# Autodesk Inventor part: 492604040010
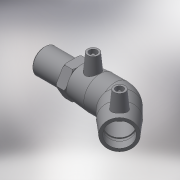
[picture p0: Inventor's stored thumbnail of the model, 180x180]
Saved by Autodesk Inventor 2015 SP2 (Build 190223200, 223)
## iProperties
Created: 2017-06
Part Number: 492604040010
Material: Generic
Description: PLASSON 45° ELBOW TRANSITION MALE 40-1"
Document SubType Name: Modeling
Designer: KIM
Mass: 190.034 g
Surface Area: 453.41 cm^2
Volume: 190.034 cm^3
Density: 1 g/cm^3
Appearance: Default
Author: KIM
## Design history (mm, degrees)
derived "492604.ipt"
feature "Solid1::492604.ipt"
tag "TaggingFeature1"
body "Solid1"
other parameters: "d2" = 56, "d4" = 27, "d5" = 50.4, "d8" = 168 deg, "d10" = 17.6, "d11" = 5.86667, "d29" = 47, "d30" = 15, "d31" = 37.8, "d34" = 5 deg, "d41" = 4, "d42" = 14, "d43" = 0, "d50" = 26, "d51" = 17.6, "d52" = 45.32, "d54" = 135 deg, "d86" = 25.2, "d87" = 135 deg, "d88" = 108, "d90" = 44, "d91" = 0, "d92" = 44, "d93" = 0, "d101" = 3, "d102" = 0, "d107" = 0.1, "d108" = 29, "d109" = 33.249, "d110" = 34, "d111" = 8.5, "d112" = 56, "d113" = 23.2743, "d114" = 30.6, "d116" = 1.68, "d122" = 0, "d123" = 1.66245, "L_" = 142, "L_1" = 44, "D_" = 29, "A_" = 47, "d_2" = 12, "L_2" = 34, "R_" = 33.249, "D_1" = 56
